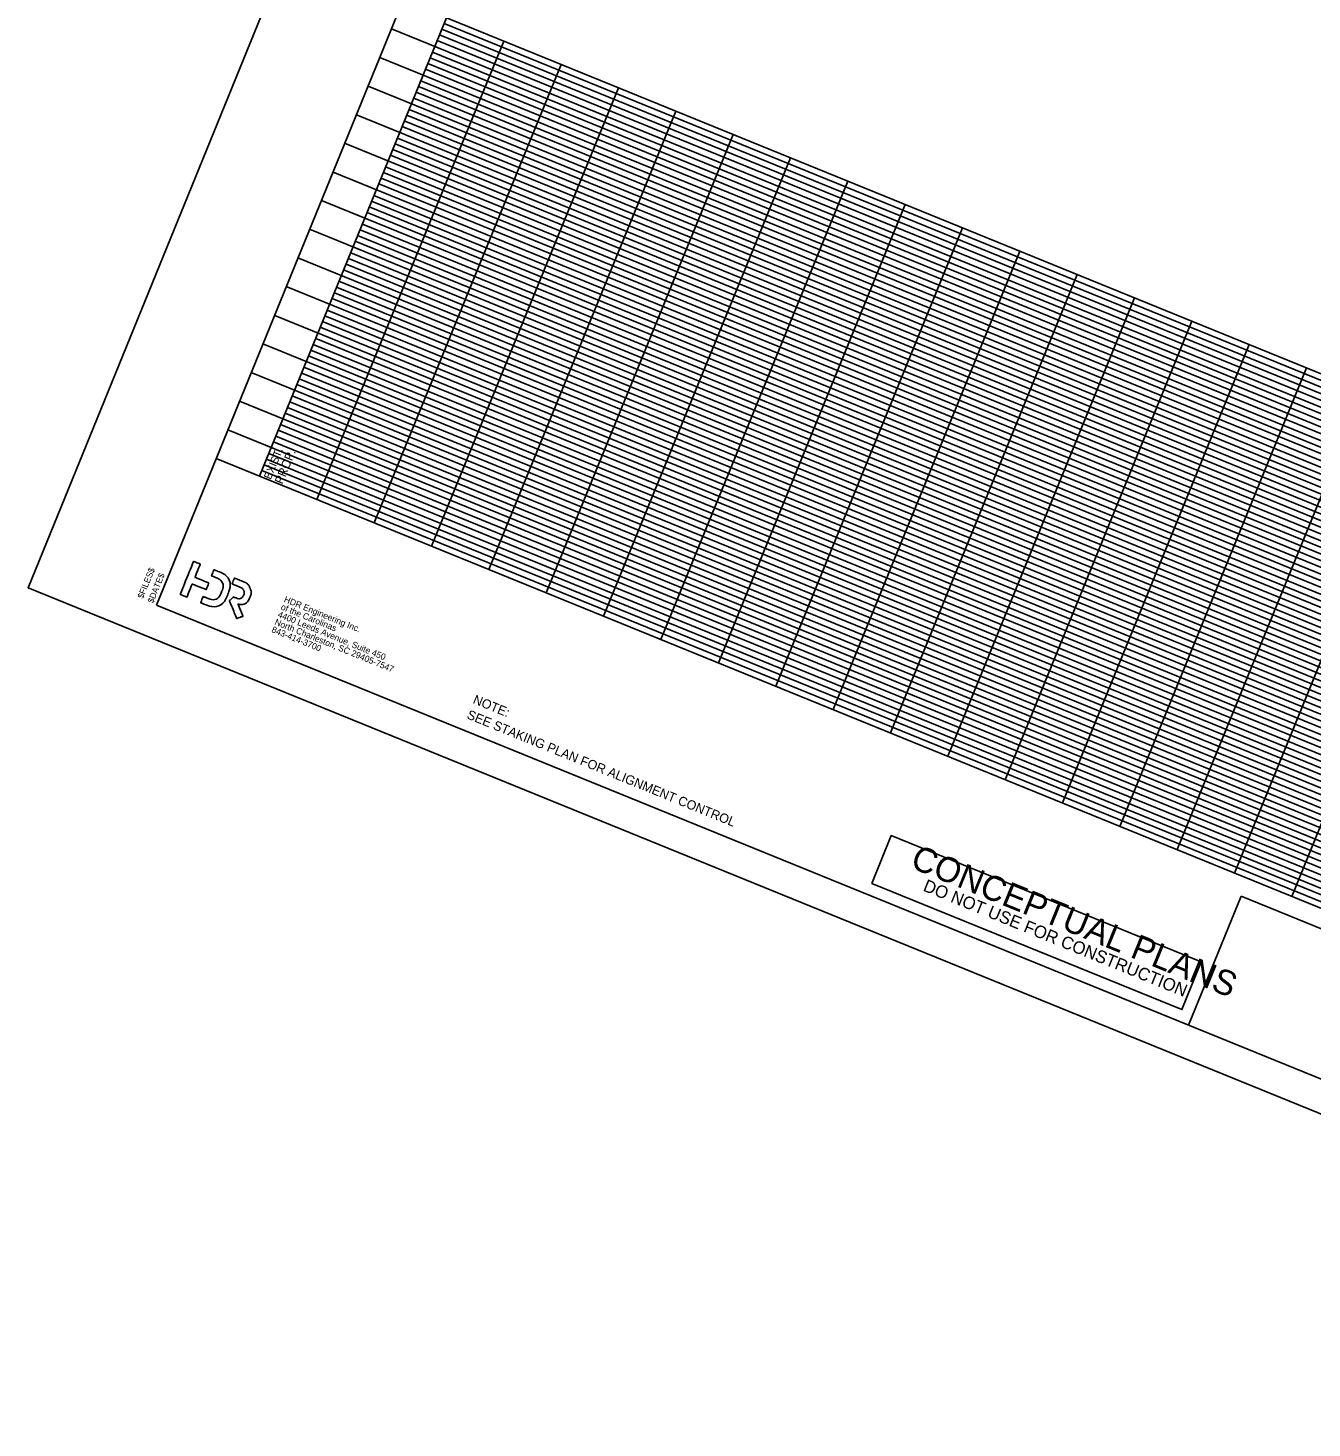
# Model space of a CAD drawing. Extents: x 2163359 to 2165441, y 212341 to 214039.
# Drawn here: x 2163359 to 2164396, y 212341 to 213472 of the extents above; entities that cross this region are included whole.
import ezdxf

# ---------------------------------------------------------------- set-up
doc = ezdxf.new("R2010")
doc.units = 0
for name, color, linetype in [('RD_DDB_StripGrade', 7, 'Continuous'), ('RD_SHT_Bndy', 7, 'Continuous'), ('RD_SHT_ID', 7, 'Continuous'), ('RD_SHT_IplotShp', 7, 'Continuous'), ('RD_SHT_Misc1', 7, 'Continuous'), ('RD_SHT_Misc4', 7, 'Continuous'), ('RD_SHT_MjGrid', 7, 'Continuous'), ('RD_SHT_SubGrid', 7, 'Continuous'), ('RD_SHT_TX', 7, 'Continuous')]:
    doc.layers.add(name, color=color, linetype=linetype)

msp = doc.modelspace()

# ---------------------------------------------------------------- linework, layer by layer
at = {"layer": 'RD_SHT_Bndy'}
for p, q in [((2163859.3, 213978.6), (2163463.2, 213006.1)), ((2163463.2, 213006.1), (2165014.5, 212374.3))]:
    msp.add_line(p, q, dxfattribs=at)
for points in [[(2163662.3, 213494.9), (2165213.6, 212863.1)], [(2163546.4, 213110.2), (2163697.3, 213480.7)], [(2163511.4, 213124.5), (2165062.7, 212492.6)]]:
    msp.add_lwpolyline(points, dxfattribs=at)
at = {"layer": 'RD_SHT_ID'}
for points in [[(2163505.4, 213024), (2163505.4, 213024), (2163494.2, 213028.5), (2163494.2, 213028.5), (2163494.2, 213028.5), (2163494.2, 213028.5), (2163498.5, 213039.2), (2163498.5, 213039.2), (2163498.5, 213039.2), (2163498.5, 213039.2), (2163493.1, 213041.4), (2163493.1, 213041.4), (2163493.1, 213041.4), (2163493.1, 213041.4), (2163482.3, 213014.7), (2163482.3, 213014.7), (2163482.3, 213014.7), (2163482.3, 213014.7), (2163487.7, 213012.5), (2163487.7, 213012.5), (2163487.7, 213012.5), (2163487.7, 213012.5), (2163492, 213023.2), (2163492, 213023.2), (2163492, 213023.2), (2163492, 213023.2), (2163503.3, 213018.6), (2163503.3, 213018.6), (2163503.3, 213018.6), (2163503.3, 213018.6), (2163505.4, 213024), (2163505.4, 213024)], [(2163520.7, 213014.6), (2163520.7, 213014.6), (2163520.7, 213014.7), (2163520.7, 213014.7), (2163520.7, 213014.7), (2163520.7, 213014.7), (2163520.7, 213014.7), (2163520.7, 213014.7), (2163520.7, 213014.7), (2163523.8, 213022.4), (2163520.5, 213030.3), (2163512.8, 213033.4), (2163512.8, 213033.4), (2163512.8, 213033.4), (2163509.6, 213034.7), (2163509.6, 213034.7), (2163509.6, 213034.7), (2163509.6, 213034.7), (2163507.6, 213029.7), (2163507.6, 213029.7), (2163507.6, 213029.7), (2163507.6, 213029.7), (2163510.7, 213028.4), (2163510.7, 213028.4), (2163510.7, 213028.4), (2163515.7, 213026.4), (2163517.7, 213021.6), (2163515.7, 213016.7), (2163515.7, 213016.7), (2163513.7, 213011.8), (2163508.9, 213009.7), (2163504, 213011.7), (2163504, 213011.7), (2163504, 213011.7), (2163500.8, 213013), (2163500.8, 213013), (2163500.8, 213013), (2163500.8, 213013), (2163498.8, 213008), (2163498.8, 213008), (2163498.8, 213008), (2163498.8, 213008), (2163501.9, 213006.7), (2163501.9, 213006.7), (2163501.9, 213006.7), (2163509.6, 213003.6), (2163517.5, 213006.9), (2163520.7, 213014.6), (2163520.7, 213014.6), (2163520.7, 213014.6), (2163520.7, 213014.6), (2163520.7, 213014.6), (2163520.7, 213014.6), (2163520.7, 213014.6), (2163520.7, 213014.6), (2163520.7, 213014.6)], [(2163524.2, 213023.2), (2163524.2, 213023.2), (2163530.2, 213020.7), (2163530.2, 213020.7), (2163530.2, 213020.7), (2163532, 213020), (2163533.1, 213019.1), (2163533.6, 213017.9), (2163533.6, 213017.9), (2163534.1, 213016.7), (2163534.1, 213015.5), (2163533.6, 213014.3), (2163533.6, 213014.3), (2163532.5, 213011.6), (2163529.5, 213011), (2163527, 213012), (2163527, 213012), (2163527, 213012), (2163525.4, 213012.6), (2163525.4, 213012.6), (2163525.4, 213012.6), (2163525.4, 213012.6), (2163522.1, 213009.6), (2163522.1, 213009.6), (2163522.1, 213009.6), (2163522.1, 213009.6), (2163527.8, 212995.3), (2163527.8, 212995.3), (2163527.8, 212995.3), (2163527.8, 212995.3), (2163533, 212997), (2163533, 212997), (2163533, 212997), (2163533, 212997), (2163528.9, 213006.9), (2163528.9, 213006.9), (2163528.9, 213006.9), (2163533, 213006), (2163537.1, 213008.5), (2163538.6, 213012.2), (2163538.6, 213012.2), (2163539.7, 213015), (2163539.8, 213017.4), (2163538.6, 213020.1), (2163538.6, 213020.1), (2163537.3, 213022.9), (2163535.2, 213024.3), (2163531.8, 213025.7), (2163531.8, 213025.7), (2163531.8, 213025.7), (2163526.1, 213028), (2163526.1, 213028), (2163526.1, 213028), (2163526.1, 213028), (2163524.2, 213023.2), (2163524.2, 213023.2)]]:
    msp.add_open_spline(points, degree=3, dxfattribs=at)
at = {"layer": 'RD_SHT_IplotShp'}
msp.add_lwpolyline([(2163774.3, 214038.9), (2165441.4, 213359.9), (2165026.4, 212341.2), (2163359.4, 213020.1)], close=True, dxfattribs=at)
at = {"layer": 'RD_SHT_Misc4'}
for p, q in [((2164296.5, 212666.7), (2164339, 212770.9)), ((2164339, 212770.9), (2164547.3, 212686))]:
    msp.add_line(p, q, dxfattribs=at)
at = {"layer": 'RD_SHT_MjGrid'}
for p, q in [((2163743.6, 213461.8), (2163592.7, 213091.4)), ((2163789.9, 213443), (2163639, 213072.5)), ((2163836.2, 213424.1), (2163685.3, 213053.6)), ((2163882.5, 213405.2), (2163731.6, 213034.8)), ((2163928.8, 213386.4), (2163777.9, 213015.9)), ((2163975.1, 213367.5), (2163824.2, 212997.1)), ((2164021.4, 213348.7), (2163870.5, 212978.2)), ((2164067.7, 213329.8), (2163916.9, 212959.3)), ((2164114, 213310.9), (2163963.2, 212940.5)), ((2164160.4, 213292.1), (2164009.5, 212921.6)), ((2164206.7, 213273.2), (2164055.8, 212902.8)), ((2164253, 213254.3), (2164102.1, 212883.9)), ((2164299.3, 213235.5), (2164148.4, 212865)), ((2164345.6, 213216.6), (2164194.7, 212846.2)), ((2164391.9, 213197.8), (2164241, 212827.3)), ((2164438.2, 213178.9), (2164287.3, 212808.5)), ((2164484.5, 213160), (2164333.6, 212789.6)), ((2164530.8, 213141.2), (2164379.9, 212770.7))]:
    msp.add_line(p, q, dxfattribs=at)
for points in [[(2163652.9, 213471.8), (2165204.1, 212839.9)], [(2163643.4, 213448.6), (2165194.7, 212816.8)], [(2163634, 213425.5), (2165185.3, 212793.6)], [(2163624.6, 213402.3), (2165175.8, 212770.5)], [(2163615.1, 213379.2), (2165166.4, 212747.3)], [(2163605.7, 213356), (2165157, 212724.2)], [(2163596.3, 213332.9), (2165147.5, 212701)], [(2163586.8, 213309.7), (2165138.1, 212677.9)], [(2163577.4, 213286.6), (2165128.7, 212654.7)], [(2163568, 213263.4), (2165119.3, 212631.6)], [(2163558.6, 213240.2), (2165109.8, 212608.4)], [(2163549.1, 213217.1), (2165100.4, 212585.3)], [(2163539.7, 213193.9), (2165091, 212562.1)], [(2163530.3, 213170.8), (2164954.5, 212590.7)], [(2163520.8, 213147.6), (2164945, 212567.6)]]:
    msp.add_lwpolyline(points, dxfattribs=at)
at = {"layer": 'RD_SHT_SubGrid'}
for p, q in [((2165177.2, 212872.5), (2163695.4, 213476)), ((2165171.5, 212858.6), (2163689.7, 213462.2)), ((2165173.4, 212863.2), (2163691.6, 213466.8)), ((2165175.3, 212867.9), (2163693.5, 213471.4)), ((2165167.8, 212849.4), (2163686, 213452.9)), ((2165162.1, 212835.5), (2163680.3, 213439)), ((2165164, 212840.1), (2163682.2, 213443.6)), ((2165165.9, 212844.7), (2163684.1, 213448.3)), ((2165158.3, 212826.2), (2163676.5, 213429.7)), ((2165152.7, 212812.3), (2163670.9, 213415.8)), ((2165154.6, 212816.9), (2163672.8, 213420.5)), ((2165156.5, 212821.6), (2163674.7, 213425.1)), ((2165148.9, 212803), (2163667.1, 213406.6)), ((2165145.1, 212793.8), (2163663.3, 213397.3)), ((2165147, 212798.4), (2163665.2, 213402)), ((2165139.5, 212779.9), (2163657.7, 213383.4)), ((2165143.3, 212789.2), (2163661.5, 213392.7)), ((2165135.7, 212770.6), (2163653.9, 213374.2)), ((2165137.6, 212775.3), (2163655.8, 213378.8)), ((2165130.1, 212756.7), (2163648.2, 213360.3)), ((2165133.8, 212766), (2163652, 213369.5)), ((2165126.3, 212747.5), (2163644.5, 213351)), ((2165128.2, 212752.1), (2163646.4, 213355.6)), ((2165120.6, 212733.6), (2163638.8, 213337.1)), ((2165124.4, 212742.8), (2163642.6, 213346.4)), ((2165116.8, 212724.3), (2163635, 213327.9)), ((2165118.7, 212729), (2163636.9, 213332.5)), ((2165111.2, 212710.4), (2163629.4, 213314)), ((2165115, 212719.7), (2163633.2, 213323.2)), ((2165107.4, 212701.2), (2163625.6, 213304.7)), ((2165109.3, 212705.8), (2163627.5, 213309.3)), ((2165105.5, 212696.5), (2163623.7, 213300.1)), ((2165098, 212678), (2163616.2, 213281.6)), ((2165099.9, 212682.6), (2163618.1, 213286.2)), ((2165101.8, 212687.3), (2163620, 213290.8)), ((2165096.1, 212673.4), (2163614.3, 213276.9)), ((2165088.6, 212654.9), (2163606.8, 213258.4)), ((2165090.4, 212659.5), (2163608.6, 213263)), ((2165092.3, 212664.1), (2163610.5, 213267.7)), ((2165086.7, 212650.2), (2163604.9, 213253.8)), ((2165079.1, 212631.7), (2163597.3, 213235.3)), ((2165081, 212636.3), (2163599.2, 213239.9)), ((2165082.9, 212641), (2163601.1, 213244.5)), ((2165077.2, 212627.1), (2163595.4, 213230.6)), ((2165069.7, 212608.6), (2163587.9, 213212.1)), ((2165071.6, 212613.2), (2163589.8, 213216.7)), ((2165073.5, 212617.8), (2163591.7, 213221.4)), ((2165067.8, 212603.9), (2163586, 213207.5)), ((2165062.2, 212590), (2163580.4, 213193.6)), ((2165064, 212594.7), (2163582.2, 213198.2)), ((2165058.4, 212580.8), (2163576.6, 213184.3)), ((2165060.3, 212585.4), (2163578.5, 213188.9)), ((2165052.7, 212566.9), (2163570.9, 213170.4)), ((2165054.6, 212571.5), (2163572.8, 213175.1)), ((2165049, 212557.6), (2163567.1, 213161.2)), ((2165050.8, 212562.3), (2163569, 213165.8)), ((2164950.7, 212581.5), (2163561.5, 213147.3)), ((2164952.6, 212586.1), (2163563.4, 213151.9)), ((2164946.9, 212572.2), (2163557.7, 213138)), ((2164948.8, 212576.8), (2163559.6, 213142.6)), ((2164941.2, 212558.3), (2163552.1, 213124.1)), ((2164943.1, 212562.9), (2163553.9, 213128.7)), ((2164937.5, 212549), (2163548.3, 213114.9)), ((2164939.4, 212553.7), (2163550.2, 213119.5))]:
    msp.add_line(p, q, dxfattribs=at)
at = {"layer": 'RD_SHT_TX'}
msp.add_lwpolyline([(2164040.8, 212781.2), (2164056.5, 212819.8), (2164306.9, 212717.8), (2164291.2, 212679.3)], close=True, dxfattribs=at)

# ---------------------------------------------------------------- texts
at = {"layer": 'RD_DDB_StripGrade'}
for s, height, p in [('EXIST.', 6.3, (2163555.4, 213107.1)), ('PROP.', 7, (2163564.8, 213103.3))]:
    msp.add_text(s, height=height, rotation=67.8388, dxfattribs=at).set_placement(p)
at = {"layer": 'RD_SHT_ID'}
for s, p in [('HDR Engineering Inc.', (2163565.6, 213008.8)), ('4400 Leeds Avenue, Suite 450', (2163560.6, 212996.6)), ('of the Carolinas', (2163563.1, 213002.7)), ('843-414-3700', (2163555.6, 212984.4)), ('North Charleston, SC 29405-7547', (2163558.1, 212990.5))]:
    msp.add_text(s, height=5.1, rotation=337.8388, dxfattribs=at).set_placement(p)
at = {"layer": 'RD_SHT_Misc1'}
for s, p in [('$FILES$', (2163452.2, 213010.9)), ('$DATE$', (2163460.4, 213007.2))]:
    msp.add_text(s, height=5, rotation=67.8388, dxfattribs=at).set_placement(p)
at = {"layer": 'RD_SHT_TX'}
for s, height, p in [('NOTE:', 7.5, (2163718.1, 212926.9)), ('SEE STAKING PLAN FOR ALIGNMENT CONTROL', 7.5, (2163713.2, 212914.7)), ('CONCEPTUAL PLANS', 20.16, (2164071, 212794.3)), ('DO NOT USE FOR CONSTRUCTION', 10.08, (2164081.5, 212775.5))]:
    msp.add_text(s, height=height, rotation=337.8388, dxfattribs=at).set_placement(p)

doc.saveas('drawing.dxf')
